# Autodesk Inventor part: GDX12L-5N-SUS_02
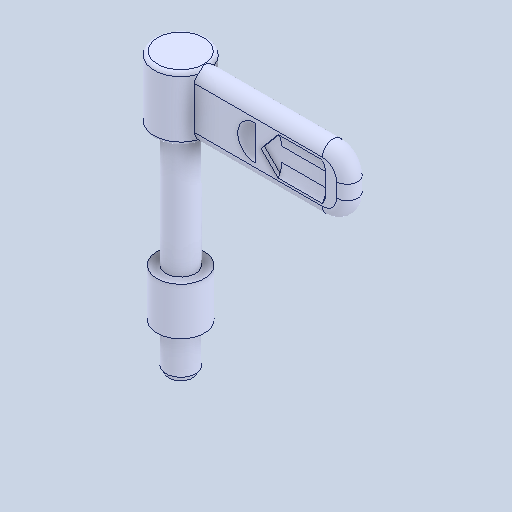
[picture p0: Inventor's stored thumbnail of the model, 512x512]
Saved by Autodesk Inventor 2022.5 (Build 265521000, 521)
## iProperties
Created: 2024-06
Part Number: GDX12L-5N-SUS_02
Material: 一般
Document SubType Name: Modeling
Designer: ImaoCorp
Density: 1 g/cm^3
Appearance: 既定
Author: ImaoCorp
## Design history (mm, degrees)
feature "GDX12L-5N-SUS_02"
node "ソリッド1"
